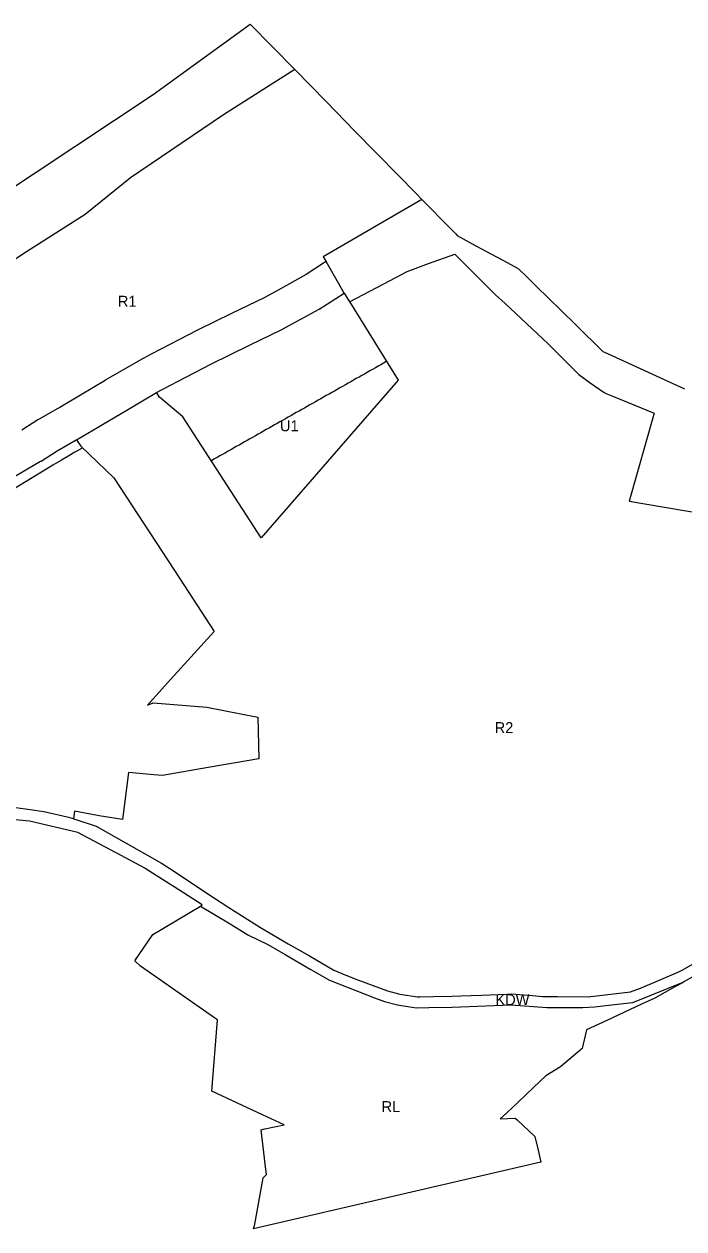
# Model space of a CAD drawing. Extents: x 7413438 to 7416393, y 5541665 to 5544118.
# Drawn here: x 7415626 to 7415988, y 5542873 to 5543535 of the extents above; entities that cross this region are included whole.
import ezdxf

# ---------------------------------------------------------------- set-up
doc = ezdxf.new("R2010")
doc.units = 0
for name, color, linetype in [('linie_rozgraniczajace', 7, 'Continuous'), ('linie_zabudowy_nieprzekraczalne', 7, 'Continuous'), ('oznaczenia_przeznaczen', 7, 'Continuous')]:
    doc.layers.add(name, color=color, linetype=linetype)

msp = doc.modelspace()

# ---------------------------------------------------------------- linework, layer by layer
at = {"layer": 'linie_rozgraniczajace'}
for p, q in [((7415696.54, 5543496.79), (7415749.89, 5543535.43)), ((7415749.89, 5543535.43), (7415774.37, 5543510.44)), ((7415774.37, 5543510.44), (7415735.34, 5543485.52)), ((7415774.37, 5543510.44), (7415791.83, 5543492.61)), ((7415592.88, 5543427.88), (7415696.54, 5543496.79)), ((7415791.83, 5543492.61), (7415807.31, 5543476.79)), ((7415735.34, 5543485.52), (7415684.06, 5543450.87)), ((7415807.31, 5543476.79), (7415831.47, 5543452.12)), ((7415684.06, 5543450.87), (7415659.19, 5543430.79)), ((7415831.47, 5543452.12), (7415840.77, 5543442.63)), ((7415844.29, 5543439.02), (7415790.01, 5543407.45)), ((7415840.77, 5543442.63), (7415841.08, 5543442.31)), ((7415841.08, 5543442.31), (7415844.29, 5543439.02)), ((7415844.29, 5543439.02), (7415848.22, 5543435.01)), ((7415848.22, 5543435.01), (7415856.22, 5543426.84)), ((7415659.19, 5543430.79), (7415626.92, 5543410.15)), ((7415856.22, 5543426.84), (7415862.86, 5543420.06)), ((7415862.86, 5543420.06), (7415863.65, 5543419.26)), ((7415863.65, 5543419.26), (7415871.98, 5543414.69)), ((7415871.98, 5543414.69), (7415879.39, 5543410.62)), ((7415626.92, 5543410.15), (7415608.04, 5543397.87)), ((7415790.01, 5543407.45), (7415791.61, 5543404.81)), ((7415847.9, 5543403.83), (7415862.42, 5543408.93)), ((7415862.42, 5543408.93), (7415878.12, 5543393.24)), ((7415879.39, 5543410.62), (7415888.68, 5543405.53)), ((7415790.7, 5543404.26), (7415780.62, 5543397.82)), ((7415791.61, 5543404.81), (7415790.7, 5543404.26)), ((7415801.65, 5543387.52), (7415791.61, 5543404.81)), ((7415823.4, 5543392.61), (7415836.18, 5543399.43)), ((7415836.18, 5543399.43), (7415847.9, 5543403.83)), ((7415888.68, 5543405.53), (7415897.25, 5543401)), ((7415897.25, 5543401), (7415902.26, 5543396.08)), ((7415780.62, 5543397.82), (7415765.27, 5543389.16)), ((7415804.55, 5543382.63), (7415823.4, 5543392.61)), ((7415878.12, 5543393.24), (7415884.82, 5543386.54)), ((7415902.26, 5543396.08), (7415907.3, 5543391.14)), ((7415765.27, 5543389.16), (7415757.52, 5543384.9)), ((7415787.78, 5543378.69), (7415801.65, 5543387.52)), ((7415801.65, 5543387.52), (7415804.55, 5543382.63)), ((7415884.82, 5543386.54), (7415889.97, 5543381.76)), ((7415907.3, 5543391.14), (7415920.49, 5543378.23)), ((7415757.52, 5543384.9), (7415739.7, 5543376.23)), ((7415804.55, 5543382.63), (7415804.62, 5543382.5)), ((7415804.62, 5543382.5), (7415831.28, 5543339.63)), ((7415889.97, 5543381.76), (7415913.72, 5543359.7)), ((7415739.7, 5543376.23), (7415721.05, 5543367.11)), ((7415766.93, 5543367.26), (7415787.78, 5543378.69)), ((7415920.49, 5543378.23), (7415928.98, 5543369.91)), ((7415721.05, 5543367.11), (7415695.55, 5543353.97)), ((7415749.97, 5543358.97), (7415766.93, 5543367.26)), ((7415928.98, 5543369.91), (7415943.78, 5543355.42)), ((7415913.72, 5543359.7), (7415930.47, 5543342.74)), ((7415695.55, 5543353.97), (7415688.77, 5543350.32)), ((7415728.29, 5543348.36), (7415749.97, 5543358.97)), ((7415943.78, 5543355.42), (7415944.72, 5543354.97)), ((7415944.72, 5543354.97), (7415948.65, 5543353.12)), ((7415948.65, 5543353.12), (7415964.26, 5543346)), ((7415688.5, 5543350.17), (7415670.29, 5543339.61)), ((7415688.73, 5543350.3), (7415688.5, 5543350.17)), ((7415688.77, 5543350.32), (7415688.73, 5543350.3)), ((7415701.63, 5543334.53), (7415728.29, 5543348.36)), ((7415670.29, 5543339.61), (7415670.13, 5543339.51)), ((7415831.28, 5543339.63), (7415755.89, 5543252.9)), ((7415930.47, 5543342.74), (7415936.83, 5543338.21)), ((7415964.26, 5543346), (7415988.61, 5543334.9)), ((7415670.13, 5543339.51), (7415656.7, 5543331.39)), ((7415698.4, 5543332.79), (7415701.63, 5543334.53)), ((7415936.83, 5543338.21), (7415944.47, 5543332.79)), ((7415656.7, 5543331.39), (7415645.22, 5543324.68)), ((7415677.1, 5543320.23), (7415698.4, 5543332.79)), ((7415700.09, 5543330.31), (7415698.4, 5543332.79)), ((7415712.94, 5543319.47), (7415700.09, 5543330.31)), ((7415944.47, 5543332.79), (7415946, 5543332.16)), ((7415946, 5543332.16), (7415949.6, 5543330.67)), ((7415949.6, 5543330.67), (7415971.98, 5543321.47)), ((7415644.25, 5543324.12), (7415633.61, 5543317.97)), ((7415645.22, 5543324.68), (7415644.25, 5543324.12)), ((7415668.67, 5543315.26), (7415676.86, 5543320.09)), ((7415676.86, 5543320.09), (7415677.07, 5543320.21)), ((7415677.07, 5543320.21), (7415677.1, 5543320.23)), ((7415971.98, 5543321.47), (7415958.11, 5543273.01)), ((7415633.26, 5543317.76), (7415624.41, 5543312.15)), ((7415633.61, 5543317.97), (7415633.26, 5543317.76)), ((7415654.42, 5543306.9), (7415666.85, 5543314.16)), ((7415666.85, 5543314.16), (7415666.98, 5543314.24)), ((7415666.98, 5543314.24), (7415668.67, 5543315.26)), ((7415755.89, 5543252.9), (7415712.94, 5543319.47)), ((7415643.79, 5543300.75), (7415654.28, 5543306.81)), ((7415654.28, 5543306.81), (7415654.32, 5543306.84)), ((7415654.32, 5543306.84), (7415654.42, 5543306.9)), ((7415654.42, 5543306.9), (7415656.82, 5543303.41)), ((7415634.98, 5543295.17), (7415643.79, 5543300.75)), ((7415656.82, 5543303.41), (7415675.06, 5543285.9)), ((7415620.46, 5543286.58), (7415634.72, 5543295.01)), ((7415634.72, 5543295.01), (7415634.98, 5543295.17)), ((7415675.06, 5543285.9), (7415711.35, 5543230.17)), ((7415958.11, 5543273.01), (7415998.1, 5543266.23)), ((7415711.35, 5543230.17), (7415730.11, 5543201.36)), ((7415730.11, 5543201.36), (7415704.55, 5543173.22)), ((7415704.55, 5543173.22), (7415693.4, 5543160.94)), ((7415693.4, 5543160.94), (7415696.65, 5543162.17)), ((7415696.65, 5543162.17), (7415726.12, 5543159.76)), ((7415726.12, 5543159.76), (7415754.17, 5543154.29)), ((7415754.17, 5543154.29), (7415754.65, 5543131.44)), ((7415754.65, 5543131.44), (7415726.9, 5543126.62)), ((7415683.09, 5543123.92), (7415679.81, 5543098.04)), ((7415697.04, 5543122.67), (7415683.09, 5543123.92)), ((7415701.7, 5543122.26), (7415697.04, 5543122.67)), ((7415726.9, 5543126.62), (7415701.7, 5543122.26)), ((7415629.01, 5543103.32), (7415621.18, 5543104.4)), ((7415636.49, 5543102.29), (7415629.01, 5543103.32)), ((7415651, 5543099.03), (7415636.49, 5543102.29)), ((7415653.39, 5543102.57), (7415652.77, 5543098.45)), ((7415665.98, 5543100.23), (7415653.39, 5543102.57)), ((7415628.64, 5543097.08), (7415607.16, 5543099.16)), ((7415655.19, 5543090.88), (7415628.64, 5543097.08)), ((7415652.77, 5543098.45), (7415651, 5543099.03)), ((7415652.77, 5543098.45), (7415654.04, 5543098.03)), ((7415654.04, 5543098.03), (7415665.31, 5543094.32)), ((7415666.88, 5543100.09), (7415665.98, 5543100.23)), ((7415679.81, 5543098.04), (7415666.88, 5543100.09)), ((7415681.68, 5543076.76), (7415655.19, 5543090.88)), ((7415665.31, 5543094.32), (7415672.13, 5543090.54)), ((7415672.13, 5543090.54), (7415693.17, 5543078.63)), ((7415691.93, 5543071.3), (7415681.68, 5543076.76)), ((7415693.17, 5543078.63), (7415701.17, 5543074.02)), ((7415692.21, 5543071.12), (7415691.93, 5543071.3)), ((7415705.78, 5543062.44), (7415692.21, 5543071.12)), ((7415701.17, 5543074.02), (7415708.25, 5543069.38)), ((7415708.25, 5543069.38), (7415725.59, 5543057.87)), ((7415708.14, 5543060.93), (7415705.78, 5543062.44)), ((7415723.6, 5543051.04), (7415708.14, 5543060.93)), ((7415725.59, 5543057.87), (7415738.2, 5543049.72)), ((7415696.46, 5543034.78), (7415722.65, 5543050.47)), ((7415722.65, 5543050.47), (7415723.6, 5543051.04)), ((7415722.65, 5543050.47), (7415738.9, 5543040.61)), ((7415738.2, 5543049.72), (7415755.54, 5543038.61)), ((7415738.9, 5543040.61), (7415747.21, 5543035.56)), ((7415747.21, 5543035.56), (7415748.59, 5543034.6)), ((7415755.54, 5543038.61), (7415770.77, 5543029.73)), ((7415686.58, 5543020.36), (7415696.46, 5543034.78)), ((7415748.59, 5543034.6), (7415759.55, 5543029.26)), ((7415759.55, 5543029.26), (7415769.06, 5543023.78)), ((7415770.77, 5543029.73), (7415782.47, 5543022.99)), ((7415986.94, 5543015.08), (7416011.39, 5543028.84)), ((7415769.06, 5543023.78), (7415782.91, 5543015.81)), ((7415782.47, 5543022.99), (7415795.89, 5543015.25)), ((7415689.57, 5543017.43), (7415686.58, 5543020.36)), ((7415729.78, 5542989.34), (7415689.57, 5543017.43)), ((7415782.91, 5543015.81), (7415793.43, 5543009.78)), ((7415795.89, 5543015.25), (7415802.55, 5543012.53)), ((7415984.15, 5543013.64), (7415986.94, 5543015.08)), ((7416001.1, 5543015.87), (7415987.94, 5543008.51)), ((7415793.43, 5543009.78), (7415818.32, 5543000.02)), ((7415802.55, 5543012.53), (7415808.5, 5543010.13)), ((7415808.5, 5543010.13), (7415825.42, 5543003.75)), ((7415960.29, 5542997.4), (7415987.94, 5543008.51)), ((7415964.34, 5543005.28), (7415984.15, 5543013.64)), ((7415987.91, 5543008.49), (7415986, 5543007.43)), ((7415987.94, 5543008.51), (7415987.91, 5543008.49)), ((7415825.42, 5543003.75), (7415832.19, 5543001.98)), ((7415832.19, 5543001.98), (7415841.85, 5543000.49)), ((7415877, 5543001.38), (7415891.05, 5543002.08)), ((7415891.05, 5543002.08), (7415893.55, 5543002.2)), ((7415893.55, 5543002.2), (7415905.04, 5543001.22)), ((7415935.71, 5543000.6), (7415958.91, 5543003.27)), ((7415958.91, 5543003.27), (7415964.34, 5543005.28)), ((7415983.38, 5543005.96), (7415972.34, 5542999.79)), ((7415985.04, 5543006.89), (7415983.38, 5543005.96)), ((7415986, 5543007.43), (7415985.04, 5543006.89)), ((7415818.32, 5543000.02), (7415823.75, 5542997.99)), ((7415823.75, 5542997.99), (7415830.95, 5542996.1)), ((7415830.95, 5542996.1), (7415841.12, 5542994.53)), ((7415841.85, 5543000.49), (7415843.13, 5543000.52)), ((7415843.13, 5543000.52), (7415850.66, 5543000.68)), ((7415850.66, 5543000.68), (7415860.68, 5543000.89)), ((7415860.68, 5543000.89), (7415865.66, 5543001)), ((7415860.91, 5542994.9), (7415879.48, 5542995.5)), ((7415865.66, 5543001), (7415877, 5543001.38)), ((7415879.48, 5542995.5), (7415893.42, 5542996.19)), ((7415893.42, 5542996.19), (7415912.98, 5542994.73)), ((7415905.04, 5543001.22), (7415910.65, 5543000.74)), ((7415910.65, 5543000.74), (7415918.79, 5543000.7)), ((7415918.79, 5543000.7), (7415935.71, 5543000.6)), ((7415939.07, 5542994.98), (7415951.8, 5542996.54)), ((7415965.06, 5542996.41), (7415949.12, 5542989)), ((7415951.8, 5542996.54), (7415960.1, 5542997.37)), ((7415960.1, 5542997.37), (7415960.27, 5542997.5)), ((7415960.27, 5542997.5), (7415960.29, 5542997.4)), ((7415972.34, 5542999.79), (7415965.06, 5542996.41)), ((7415731.96, 5542987.81), (7415729.78, 5542989.34)), ((7415841.12, 5542994.53), (7415848.18, 5542994.62)), ((7415848.18, 5542994.62), (7415860.91, 5542994.9)), ((7415912.98, 5542994.73), (7415932.79, 5542994.62)), ((7415932.79, 5542994.62), (7415939.07, 5542994.98)), ((7415948.34, 5542988.64), (7415934.76, 5542982.34)), ((7415949.12, 5542989), (7415948.34, 5542988.64)), ((7415728.85, 5542948.67), (7415731.96, 5542987.81)), ((7415934.76, 5542982.34), (7415932.31, 5542972.15)), ((7415932.31, 5542972.15), (7415920.39, 5542962.1)), ((7415920.39, 5542962.1), (7415912.42, 5542957.12)), ((7415912.42, 5542957.12), (7415905.6, 5542950.66)), ((7415756.62, 5542935.7), (7415728.85, 5542948.67)), ((7415905.6, 5542950.66), (7415897.19, 5542942.69)), ((7415897.19, 5542942.69), (7415890.92, 5542936.75)), ((7415768.55, 5542930.13), (7415756.62, 5542935.7)), ((7415890.92, 5542936.75), (7415887.34, 5542933.37)), ((7415757.98, 5542927.85), (7415768.55, 5542930.13)), ((7415887.34, 5542933.37), (7415895.61, 5542933.84)), ((7415895.61, 5542933.84), (7415896.63, 5542932.88)), ((7415896.63, 5542932.88), (7415906.35, 5542923.67)), ((7415756.04, 5542927.43), (7415757.98, 5542927.85)), ((7415758.48, 5542905.65), (7415756.04, 5542927.43)), ((7415906.35, 5542923.67), (7415908.12, 5542916.17)), ((7415908.12, 5542916.17), (7415909.64, 5542909.66)), ((7415909.64, 5542909.66), (7415751.74, 5542872.91)), ((7415757, 5542901.04), (7415758.79, 5542902.87)), ((7415758.79, 5542902.87), (7415758.48, 5542905.65)), ((7415752.5, 5542875.55), (7415757, 5542901.04)), ((7415751.74, 5542872.91), (7415752.5, 5542875.55))]:
    msp.add_line(p, q, dxfattribs=at)
at = {"layer": 'linie_zabudowy_nieprzekraczalne'}
for points, degree in [([(7415824.71, 5543349.81), (7415728.79, 5543295.44)], 1), ([(7415657.6, 5543302.19), (7415645.23, 5543296.35), (7415476.29, 5543190.53), (7415443.93, 5543170.24)], 3)]:
    msp.add_open_spline(points, degree=degree, dxfattribs=at)

# ---------------------------------------------------------------- texts
at = {"layer": 'oznaczenia_przeznaczen'}
for s, p in [('R1', (7415677.19, 5543380.03)), ('U1', (7415766.29, 5543311.51)), ('R2', (7415884.28, 5543145.59)), ('KDW', (7415884.69, 5542995.95)), ('RL', (7415822.13, 5542937.17))]:
    msp.add_text(s, height=6, dxfattribs=at).set_placement(p)

doc.saveas('drawing.dxf')
